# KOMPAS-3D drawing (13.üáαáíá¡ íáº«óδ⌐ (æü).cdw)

Referenced files: 13.Барабан базовый (СБ).cdw
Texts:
  Приводной барабан - базовый вариант
  Freeman
  Текст на чертеже
  Размерные надписи
  Шероховатость
  Линия-выноска #1
  Линия-выноска #2
  Линия-выноска #3
  Отклонения формы и база
  Заголовок таблицы
  Ячейка таблицы
  Стрелка вида
  Обозначение изменения
  Фигурная скобка
  Номер узла
  Марка координационной оси
  VRCB
  Выносная надпись
  Обозначение узла
  Марка/позиционное обозначение с линией-выноской
  Марка/позиционное обозначение на линии
  Марка/позиционное обозначение без линии-выноски
  x 9отв.
  отв.
  Андриянов А.
  Приводной барабан -
  базовый вариант
  СФУ ИНГ НГ06-04
Dimensions and other numbers on the sheet: 7; 2150; 480; 1050; 1; 2; 3; 4; 5; 6; 1628; 230; 265; 8; 9; 10; 11; 48; 38 x 4; 54; 34; 16; 1:1; 0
